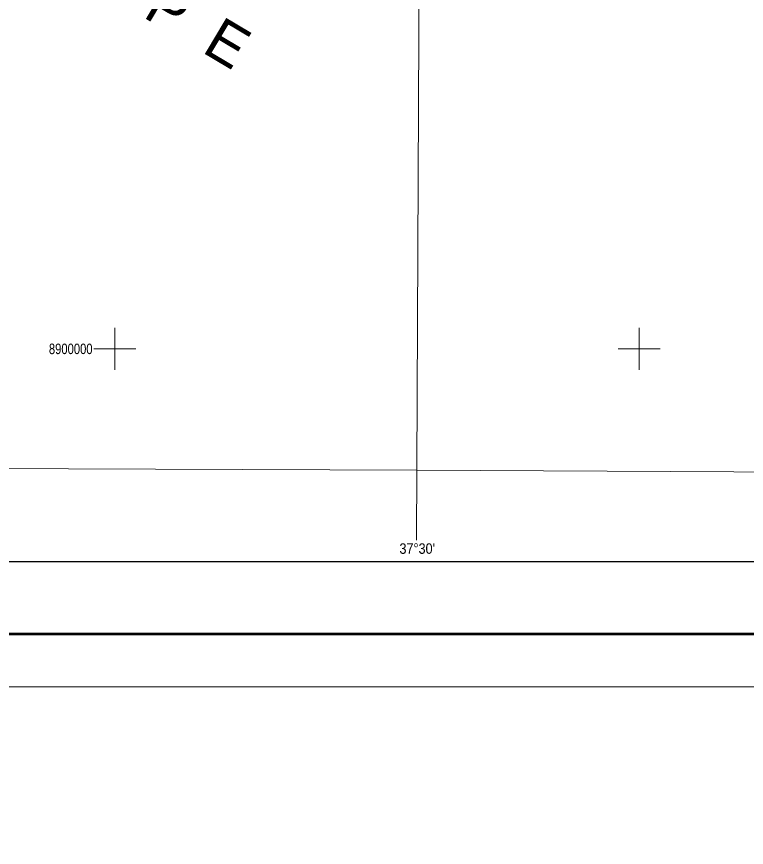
# Model space of a CAD drawing. Extents: x -1643653 to 4543381, y 1624270 to 13878484.
# Drawn here: x 645322 to 680119, y 8876229 to 8915829 of the extents above; entities that cross this region are included whole.
import ezdxf
from ezdxf.enums import TextEntityAlignment as Align

# ---------------------------------------------------------------- set-up
doc = ezdxf.new("R2010")
doc.units = 0
doc.header["$LTSCALE"] = 200
for name, color, linetype, lineweight in [('1', 7, 'Continuous', 13), ('2', 7, 'Continuous', 13), ('3', 7, 'Continuous', 13), ('60', 7, 'Continuous', 13)]:
    doc.layers.add(name, color=color, linetype=linetype, lineweight=lineweight)
for name, color, linetype in [('42', 7, 'Continuous'), ('46', 7, 'Continuous'), ('47', 7, 'Continuous')]:
    doc.layers.add(name, color=color, linetype=linetype)

msp = doc.modelspace()

# ---------------------------------------------------------------- linework, layer by layer
at = {"layer": '1'}
for points in [[(664968.2, 9023436.8), (664657.1, 8949509), (664397.1, 8890880.2)], [(564751.7, 8894587.5), (664411.9, 8894209.9), (791388.5, 8893536.2)]]:
    msp.add_lwpolyline(points, dxfattribs=at)
at = {"layer": '2'}
for p, q in [((650000, 8899000), (650000, 8901000)), ((675000, 8899000), (675000, 8901000)), ((649000, 8900000), (651000, 8900000)), ((674000, 8900000), (676000, 8900000))]:
    msp.add_line(p, q, dxfattribs=at)
at = {"layer": '3'}
msp.add_lwpolyline([(842807.3, 9032387.8), (842807.3, 8883887.8), (553961.7, 8883887.8), (553961.7, 9032387.8)], close=True, dxfattribs=at)
at = {"layer": '3', "lineweight": 53}
msp.add_lwpolyline([(840307.3, 9029887.8), (840307.3, 8886387.8), (560211.7, 8886387.8), (560211.7, 9029887.8)], close=True, dxfattribs=at)
at = {"layer": '3', "lineweight": 25}
msp.add_lwpolyline([(563033.9, 9026438.8), (793061.1, 9026438.8), (793495.6, 8889836.8), (563468.3, 8889836.8)], close=True, dxfattribs=at)
at = {"layer": '60', "lineweight": 25}
msp.add_spline([(814781, 9009175.5), (814787.2, 9009173.4), (814796.9, 9009173.4), (814799.4, 9009172.4), (814805.1, 9009174.5), (814805.6, 9009176.5), (814811.7, 9009179.5), (814811.7, 9009179.5), (814801.5, 9009181), (814790.7, 9009181.5), (814784.1, 9009183.1), (814777.4, 9009185.1), (814778.4, 9009175.5)], degree=3, dxfattribs=at)

# ---------------------------------------------------------------- texts
at = {"layer": '42'}
msp.add_text('S  E  R  G  I  P  E', height=2000, rotation=329.237, dxfattribs=at).set_placement((637761.3, 8923891.3))
at = {"layer": '46', "width": 0.9}
msp.add_text("37°30'", height=500, dxfattribs=at).set_placement((664424.4, 8890221.9), align=Align.CENTER)
at = {"layer": '47', "width": 0.8}
msp.add_text('8900000', height=500, dxfattribs=at).set_placement((647902.6, 8899742), align=Align.CENTER)

doc.saveas('drawing.dxf')
